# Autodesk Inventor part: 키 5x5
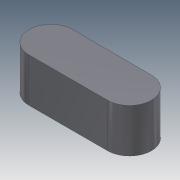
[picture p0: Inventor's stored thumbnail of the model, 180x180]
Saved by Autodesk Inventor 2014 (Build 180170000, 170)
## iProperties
Company: 한국ATC센터
Created: 2014-10
Part Number: 키 5x5
Document SubType Name: Modeling
Designer: KYOUNG IL JANG
Density: 1 g/cm^3
Mass: 0.323175 g
Surface Area: 2.9781 cm^2
Volume: 0.323175 cm^3
Material: 일반
Appearance: 강철 - 광택
Author: KYOUNG IL JANG
Revision Number: 1
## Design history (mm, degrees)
sketch "스케치1"
  geometry: L1 (-4.5, -2.5)-(4.5, -2.5); L2 (4.5, 2.5)-(-4.5, 2.5); A1 r 2.5 centre (4.5, 0) between (4.5, -2.5) and (4.5, 2.5); A2 r 2.5 centre (-4.5, 0) between (-4.5, 2.5) and (-4.5, -2.5); 2 further points
  constraints: 4 end point, 4 point on circle, 4 tangent, 2 centre point, 1 horizontal, 1 horizontal alignment, 1 midpoint, 1 parallel, 1 vertical alignment
  dimensions: "d0" = 5 distance between parallel lines of L1 L2; "d1" = 14 dimension on A1 A2
extrude "돌출1" new body sketch "스케치1" stored distance "d2" = 5; taper "d3" = 0 deg
node "솔리드1"
